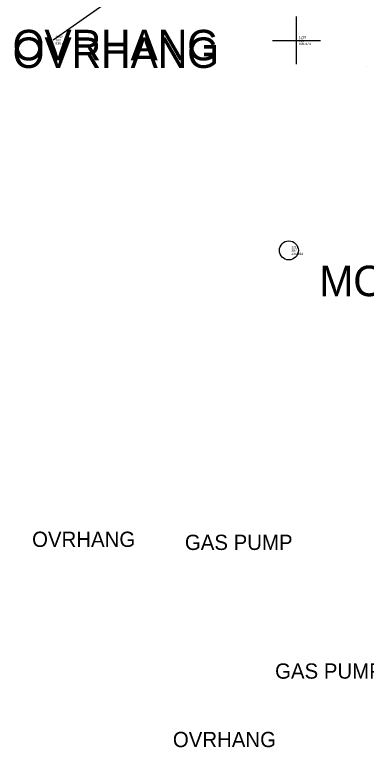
# Model space of a CAD drawing. Extents: x 5447 to 709667, y 4528 to 375505.
# Drawn here: x 706264.4 to 706301.3, y 374929.8 to 375006.6 of the extents above; entities that cross this region are included whole.
import ezdxf

# ---------------------------------------------------------------- set-up
doc = ezdxf.new("R2010")
doc.units = 0
for name, color, linetype in [('SV_NODES_ACTIVE_POINT', 7, 'Continuous'), ('SV_NODES_DESCRIPTION', 7, 'Continuous'), ('SV_NODES_ELEVATION', 7, 'Continuous'), ('SV_NODES_PT_NUMBER', 7, 'Continuous'), ('SV_ROAD_CONCRD', 7, 'Continuous'), ('SV_SURF_SPOT', 7, 'Continuous'), ('SV_SURVEY_NOTES', 7, 'Continuous'), ('SV_WATR_WATER_TX', 7, 'Continuous'), ('SV_WATR_WELL', 7, 'Continuous')]:
    doc.layers.add(name, color=color, linetype=linetype)

msp = doc.modelspace()

# ---------------------------------------------------------------- linework, layer by layer
at = {"layer": 'SV_NODES_ACTIVE_POINT'}
for p, q in [((706268.411, 375003.899), (706268.411, 375003.899)), ((706301.274, 375001.162), (706301.274, 375001.162))]:
    msp.add_line(p, q, dxfattribs=at)
at = {"layer": 'SV_ROAD_CONCRD'}
msp.add_lwpolyline([(706306.052, 375031.837), (706305.665, 375030.015), (706290.248, 375019.221), (706268.411, 375003.899)], dxfattribs=at)
at = {"layer": 'SV_SURF_SPOT'}
for p, q in [((706293.947, 375001.385), (706293.947, 375006.387)), ((706291.446, 375003.886), (706296.448, 375003.886)), ((706293.947, 375003.886), (706293.947, 375003.886))]:
    msp.add_line(p, q, dxfattribs=at)
at = {"layer": 'SV_WATR_WELL'}
msp.add_circle((706293.148, 374981.87), 0.994, dxfattribs=at)

# ---------------------------------------------------------------- texts
at = {"layer": 'SV_NODES_DESCRIPTION'}
for s, p in [('102', (706268.661, 375003.774)), ('515', (706294.197, 375003.761)), ('397', (706293.399, 374981.746))]:
    msp.add_text(s, height=0.25, dxfattribs=at).set_placement(p)
at = {"layer": 'SV_NODES_ELEVATION'}
for s, p in [('535.480', (706268.661, 375003.424)), ('535.474', (706294.197, 375003.411)), ('535.314', (706293.399, 374981.396))]:
    msp.add_text(s, height=0.25, dxfattribs=at).set_placement(p)
at = {"layer": 'SV_NODES_PT_NUMBER'}
for s, p in [('1092', (706268.661, 375004.124)), ('1218', (706294.197, 375004.111)), ('1219', (706293.399, 374982.096))]:
    msp.add_text(s, height=0.25, dxfattribs=at).set_placement(p)
at = {"layer": 'SV_SURVEY_NOTES'}
for s, height, p in [('OVRHANG', 3.2, (706264.182, 375001.794)), ('OVRHANG', 3.2, (706264.182, 375001.794)), ('OVRHANG', 3.2, (706264.182, 375001.794)), ('OVRHANG', 3.2, (706264.182, 375001.794)), ('OVRHANG', 3.2, (706264.182, 375001.794)), ('OVRHANG', 3.2, (706264.182, 375001.794)), ('OVRHANG', 3.2, (706264.182, 375001.794)), ('OVRHANG', 3.2, (706264.182, 375001.794)), ('OVRHANG', 3.2, (706264.182, 375000.994)), ('OVRHANG', 3.2, (706264.182, 375000.994)), ('OVRHANG', 3.2, (706264.182, 375000.994)), ('OVRHANG', 1.6, (706266.215, 374950.784)), ('GAS PUMP', 1.6, (706282.241, 374950.463)), ('GAS PUMP', 1.6, (706291.702, 374936.971)), ('OVRHANG', 1.6, (706280.982, 374929.794))]:
    msp.add_text(s, height=height, dxfattribs=at).set_placement(p)
at = {"layer": 'SV_WATR_WATER_TX'}
msp.add_text('MON. WELL', height=3.2, dxfattribs=at).set_placement((706296.349, 374977.071))

doc.saveas('drawing.dxf')
